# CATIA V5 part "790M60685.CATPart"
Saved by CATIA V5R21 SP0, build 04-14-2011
Part number: 790M60685
Bounding box of the stored display mesh (mm): x -342.5 to 342.5, y 0 to 61, z -122.5 to 122.5
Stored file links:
  C:\Users\ALI OZGUN\Desktop\alhan\790M60685.CATPart
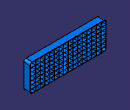
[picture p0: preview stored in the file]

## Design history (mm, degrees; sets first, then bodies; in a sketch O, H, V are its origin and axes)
Body1 (main body)
  Sketch1 on zx-plane, origin (0, 0, 0), H (-1, 0, 0), V (0, 0, 1)
    line L1 (342.5, 122.5) -> (342.5, -122.5)
    line L2 (342.5, -122.5) -> (-342.5, -122.5)
    line L3 (-342.5, -122.5) -> (-342.5, 122.5)
    line L4 (-342.5, 122.5) -> (342.5, 122.5)
    distance L4 L2 = 245
    distance L1 L3 = 685
    vertical: L1 V, L3 V
    horizontal: L2 H, L4 H
    equidistance: L1 L3 O, L2 L4 O
  Pad1: profile Sketch1, direction (0, 1, 0), length 60
  Fillet1: radius 20, on edge [face of Pad1 from Sketch1.L1 | face of Pad1 from Sketch1.L2]; edge [face of Pad1 from Sketch1.L2 | face of Pad1 from Sketch1.L3]; edge [face of Pad1 from Sketch1.L3 | face of Pad1 from Sketch1.L4]; edge [face of Pad1 from Sketch1.L4 | face of Pad1 from Sketch1.L1]
  Shell1: ExtOffset 0, Face (start face of Pad1; end face of Pad1), IntOffset 5
  Fillet2: radius 1, on edge [start face of Pad1 | face of Shell1]; edge [end face of Pad1 | face of Shell1]
  Fillet3: radius 2, on edge [start face of Pad1 | face of Pad1 from Sketch1.L1]; edge [end face of Pad1 | face of Fillet1]
  Sketch2 on start face of Pad1, origin (0, 0, 0), H (1, 0, 0), V (0, 0, 1)
    line L1 (-294, 118.5) -> (-294, -118.5)
    line L2 (-338.5, 82.5) -> (338.5, 82.5)
    projected line E9 (-338.5, -102.5) -> (-338.5, 102.5) from edge [face of Fillet2 | start face of Pad1]
    projected line E10 (-338.5, -102.5) -> (-338.5, 102.5) from edge [face of Fillet2 | start face of Pad1]
    projected line E12 (322.5, -118.5) -> (-322.5, -118.5) from edge [face of Fillet2 | start face of Pad1]
    projected line E13 (322.5, -118.5) -> (-322.5, -118.5) from edge [face of Fillet2 | start face of Pad1]
    projected line E15 (338.5, 102.5) -> (338.5, -102.5) from edge [face of Fillet2 | start face of Pad1]
    projected line E16 (338.5, 102.5) -> (338.5, -102.5) from edge [face of Fillet2 | start face of Pad1]
    projected line E18 (-322.5, 118.5) -> (322.5, 118.5) from edge [face of Fillet2 | start face of Pad1]
    projected line E19 (-322.5, 118.5) -> (322.5, 118.5) from edge [face of Fillet2 | start face of Pad1]
    reference intersected line E21 (-337.5, 102.5) -> (-337.5, -102.5) from face of Shell1
    reference intersected line E22 (322.5, 117.5) -> (-322.5, 117.5) from face of Shell1
    point P33 (-294, 118.5)
    point P34 (-338.5, 82.5)
    point P35 (-294, -118.5)
    point P36 (338.5, 82.5)
    line L3 (-338.5, 49.5) -> (338.5, 49.5)
    line L4 (-338.5, 16.5) -> (338.5, 16.5)
    line L5 (-338.5, -16.5) -> (338.5, -16.5)
    line L6 (-338.5, -49.5) -> (338.5, -49.5)
    line L7 (-338.5, -82.5) -> (338.5, -82.5)
    reference intersected line E23 (-322.5, -117.5) -> (322.5, -117.5) from face of Shell1
    line L8 (-252, 118.5) -> (-252, -118.5)
    line L9 (-210, 118.5) -> (-210, -118.5)
    line L10 (-168, 118.5) -> (-168, -118.5)
    line L11 (-126, 118.5) -> (-126, -118.5)
    line L12 (-84, 118.5) -> (-84, -118.5)
    line L13 (-42, 118.5) -> (-42, -118.5)
    line L14 (0, 118.5) -> (0, -118.5)
    line L15 (42, 118.5) -> (42, -118.5)
    line L16 (84, 118.5) -> (84, -118.5)
    line L17 (126, 118.5) -> (126, -118.5)
    line L18 (168, 118.5) -> (168, -118.5)
    line L19 (210, 118.5) -> (210, -118.5)
    line L20 (252, 118.5) -> (252, -118.5)
    line L21 (294, 118.5) -> (294, -118.5)
    reference intersected line E24 (337.5, -102.5) -> (337.5, 102.5) from face of Shell1
    distance L1 E21 = 43.5
    distance L2 E22 = 35
    distance L3 L2 = 33
    distance L3 L4 = 33
    distance L4 L5 = 33
    distance L5 L6 = 33
    distance L7 E23 = 35
    distance L6 L7 = 33 (reference)
    distance L21 L20 = 42
    distance L19 L20 = 42
    distance L18 L19 = 42
    distance L17 L18 = 42
    distance L16 L17 = 42
    distance L15 L16 = 42
    distance L14 L15 = 42
    distance L13 L14 = 42
    distance L12 L13 = 42
    distance L11 L12 = 42
    distance L10 L11 = 42
    distance L9 L10 = 42
    distance L8 L9 = 42
    distance L1 L8 = 42
    distance L21 E24 = 43.5 (reference)
    vertical: L1 V
    horizontal: L2 H
    coincidence: P33 E18, P34 E9, P35 E12, P36 E15
  Pad2: profile Sketch2, direction (0, 1, 0), length 61, thin wall 3
  Sketch3 on face of Pad2, origin (-295.5, 0, 0), H (0, -1, 0), V (0, 0, 1)
    construction line L1 (-60, -82.6932) -> (-60, 122.3068)
    construction line L2 (-60, -77.7415) -> (-60, 127.2585)
    line L3 (-60, 84) -> (-60, 88)
    line L4 (-61, 88) -> (-61, 84)
    line L5 (-60, 91.6965) -> (-60, 95.6965)
    line L6 (-61, 95.6965) -> (-61, 91.6965)
    construction line L7 (0, 91.6965) -> (-61, 91.6965)
    line L8 (-60, 91.6965) -> (-61, 91.6965)
    construction line L9 (0, 95.6965) -> (-61, 95.6965)
    construction line L10 (-60.5438, 95.6965) -> (-61, 95.6965)
    line L11 (-60, 95.6965) -> (-61, 95.6965)
    line L12 (-60, 97.893) -> (-61, 97.893)
    construction line L13 (0, 97.893) -> (-61, 97.893)
    line L14 (-60, 101.893) -> (-61, 101.893)
    construction line L15 (-60.5438, 101.893) -> (-61, 101.893)
    construction line L16 (0, 101.893) -> (-61, 101.893)
    line L17 (-60, 97.893) -> (-60, 101.893)
    line L18 (-61, 101.893) -> (-61, 97.893)
    line L19 (-60, 104.0895) -> (-61, 104.0895)
    construction line L20 (0, 104.0895) -> (-61, 104.0895)
    line L21 (-60, 108.0895) -> (-61, 108.0895)
    construction line L22 (-60.5438, 108.0895) -> (-61, 108.0895)
    construction line L23 (0, 108.0895) -> (-61, 108.0895)
    line L24 (-60, 104.0895) -> (-60, 108.0895)
    line L25 (-61, 108.0895) -> (-61, 104.0895)
    line L26 (-60, 110.286) -> (-61, 110.286)
    construction line L27 (0, 110.286) -> (-61, 110.286)
    line L28 (-60, 114.286) -> (-61, 114.286)
    construction line L29 (-60.5438, 114.286) -> (-61, 114.286)
    construction line L30 (0, 114.286) -> (-61, 114.286)
    line L31 (-60, 110.286) -> (-60, 114.286)
    line L32 (-61, 114.286) -> (-61, 110.286)
    line L33 (-60, 116.4825) -> (-61, 116.4825)
    construction line L34 (0, 116.4825) -> (-61, 116.4825)
    line L35 (-60, 120.4825) -> (-61, 120.4825)
    construction line L36 (-60.5438, 120.4825) -> (-61, 120.4825)
    construction line L37 (0, 120.4825) -> (-61, 120.4825)
    line L38 (-60, 116.4825) -> (-60, 120.4825)
    line L39 (-61, 120.4825) -> (-61, 116.4825)
    construction line L40 (0, 84) -> (-61, 84)
    line L41 (-60, 84) -> (-61, 84)
    construction line L42 (0, 88) -> (-61, 88)
    construction line L43 (-60.5438, 88) -> (-61, 88)
    line L44 (-60, 88) -> (-61, 88)
  Pocket1: profile Sketch3, direction (1, 0, 0), length 914
  Mirror1: of Pocket1, Sketch3, about xy-plane
  Sketch4 on face of Pad2, origin (-295.5, 0, 0), H (0, -1, 0), V (0, 0, 1)
    projected line E1 (-61, 81) -> (-61, 51) from edge [end face of Pad2 | face of Pad2]
    projected line E2 (-61, 55) -> (-61, 51) from edge [end face of Pad2 | face of Pad2]
    projected line E3 (0, 51) -> (-61, 51) from edge [face of Pad2 | face of Pad2]
    projected line E4 (-60, 51) -> (-61, 51) from edge [face of Pad2 | face of Pad2]
    offset line E5 (-60, 81) -> (-60, 51) from edge [end face of Pad2 | face of Pad2]
    offset line E6 (-60, 55) -> (-60, 51) from edge [end face of Pad2 | face of Pad2]
    offset line E7 (0, 55) -> (-61, 55) from edge [face of Pad2 | face of Pad2]
    offset line E8 (-60, 55) -> (-61, 55) from edge [face of Pad2 | face of Pad2]
    construction line L1 (0, 82.4462) -> (-61, 82.4462)
    construction line L2 (0, 78.5) -> (-61, 78.5)
    construction line L3 (-60.9437, 87.5779) -> (-61, 56.2)
    line L4 (-61, 60.2) -> (-61, 56.2)
    construction line L5 (0.0563, 57.5779) -> (-61, 56.2)
    line L6 (-60, 56.2) -> (-61, 56.2)
    construction line L7 (-59.9437, 87.5779) -> (-60, 56.2)
    line L8 (-60, 60.2) -> (-60, 56.2)
    construction line L9 (0.0563, 61.5779) -> (-61, 60.2)
    line L10 (-60, 60.2) -> (-61, 60.2)
    line L11 (-61, 65.4) -> (-61, 61.4)
    construction line L12 (-61, 91.4) -> (-61, 61.4)
    line L13 (-60, 61.4) -> (-61, 61.4)
    construction line L14 (0, 61.4) -> (-61, 61.4)
    line L15 (-60, 65.4) -> (-60, 61.4)
    construction line L16 (-60, 91.4) -> (-60, 61.4)
    line L17 (-60, 65.4) -> (-61, 65.4)
    construction line L18 (0, 65.4) -> (-61, 65.4)
    point P40 (-60, 66.6)
    line L19 (-61, 70.6) -> (-61, 66.6)
    construction line L20 (-61, 96.6) -> (-61, 66.6)
    line L21 (-60, 66.6) -> (-61, 66.6)
    construction line L22 (0, 66.6) -> (-61, 66.6)
    line L23 (-60, 70.6) -> (-60, 66.6)
    construction line L24 (-60, 96.6) -> (-60, 66.6)
    line L25 (-60, 70.6) -> (-61, 70.6)
    construction line L26 (0, 70.6) -> (-61, 70.6)
    line L27 (-61, 75.8) -> (-61, 71.8)
    construction line L28 (-60.9961, 102.287) -> (-61, 71.8)
    line L29 (-60, 71.8) -> (-61, 71.8)
    construction line L30 (0.0039, 72.287) -> (-61, 71.8)
    line L31 (-60, 75.8) -> (-60, 71.8)
    construction line L32 (-59.9961, 102.287) -> (-60, 71.8)
    line L33 (-60, 75.8) -> (-61, 75.8)
    construction line L34 (0.0039, 76.287) -> (-61, 75.8)
    line L35 (-61, 81) -> (-61, 77)
    construction line L36 (-61, 107) -> (-61, 77)
    line L37 (-60, 77) -> (-61, 77)
    construction line L38 (0, 77) -> (-61, 77)
    line L39 (-60, 81) -> (-60, 77)
    construction line L40 (-60, 108.3289) -> (-60, 78.3289)
    line L41 (-60, 81) -> (-61, 81)
    construction line L42 (0, 82.3289) -> (-61, 82.3289)
    distance L6 E7 = 1.2
    distance L13 L10 = 1.2
    distance P40 L17 = 1.2
    distance L29 L25 = 1.2
    coincidence: L8 E5, L15 L8, L23 L15, L31 L23
  Pocket2: profile Sketch4, direction (1, 0, 0), length 914
  RectPattern1: of Pocket2, direction 1 instances 5, spacing 33, along edge [end face of Pad2 | face of Pad2]
  Sketch5 on face of Pocket1, origin (0, 0, 84), H (1, 0, 0), V (0, 1, 0)
    projected line E1 (-338.5, 61) -> (338.5, 61) from edge [face of Pocket1 | end face of Pad2]
    projected line E2 (-292.5, 61) -> (-287.5, 61) from edge [face of Pocket1 | end face of Pad2]
    projected line E3 (-292.5, 0) -> (-292.5, 60) from edge [face of Pocket1 | face of Pad2]
    projected line E4 (-292.5, 60) -> (-292.5, 61) from edge [face of Pocket1 | face of Pad2]
    offset line E5 (-338.5, 60) -> (338.5, 60) from edge [face of Pocket1 | end face of Pad2]
    offset line E6 (-292.5, 60) -> (-287.5, 60) from edge [face of Pocket1 | end face of Pad2]
    offset line E7 (-287.5, 0) -> (-287.5, 60) from edge [face of Pocket1 | face of Pad2]
    offset line E8 (-287.5, 60) -> (-287.5, 61) from edge [face of Pocket1 | face of Pad2]
    construction line L1 (-273.9262, 0) -> (-273.9262, 60)
    line L2 (-273.9262, 60) -> (-273.9262, 61)
    construction line L3 (-321.4262, 61) -> (355.5738, 61)
    line L4 (-273.9262, 61) -> (-268.9262, 61)
    construction line L5 (-268.9262, 0) -> (-268.9262, 60)
    line L6 (-268.9262, 60) -> (-268.9262, 61)
    construction line L7 (-321.4262, 60) -> (355.5738, 60)
    line L8 (-273.9262, 60) -> (-268.9262, 60)
    line L9 (-258.5, 60) -> (-258.5, 61)
    construction line L10 (-256.8524, 0) -> (-256.8524, 60)
    line L11 (-258.5, 61) -> (-253.5, 61)
    construction line L12 (-304.3524, 61) -> (372.6476, 61)
    line L13 (-253.5, 60) -> (-253.5, 61)
    construction line L14 (-251.8524, 0) -> (-251.8524, 60)
    line L15 (-258.5, 60) -> (-253.5, 60)
    construction line L16 (-304.3524, 60) -> (372.6476, 60)
    reference intersected line E9 (-253.5, 0) -> (-253.5, 61) from face of Pad2
    coincidence: L13 E9
  Pocket3: profile Sketch5, direction (0, 0, -1), length 914
  RectPattern2: of Pocket3, direction 1 instances 14, spacing 42, along edge [face of Pocket1 | end face of Pad2]
  Sketch6 on face of Pocket1, origin (0, 0, 84), H (1, 0, 0), V (0, 1, 0)
    projected line E1 (292.5, 61) -> (338.5, 61) from edge [face of Pocket1 | end face of Pad2]
    projected line E2 (295.5, 61) -> (300.5, 61) from edge [face of Pocket1 | end face of Pad2]
    projected line E3 (295.5, 0) -> (295.5, 60) from edge [face of Pocket1 | face of Pad2]
    projected line E4 (295.5, 60) -> (295.5, 61) from edge [face of Pocket1 | face of Pad2]
    offset line E5 (300.5, 0) -> (300.5, 60) from edge [face of Pocket1 | face of Pad2]
    offset line E6 (300.5, 60) -> (300.5, 61) from edge [face of Pocket1 | face of Pad2]
    offset line E7 (292.5, 60) -> (338.5, 60) from edge [face of Pocket1 | end face of Pad2]
    offset line E8 (295.5, 60) -> (300.5, 60) from edge [face of Pocket1 | end face of Pad2]
    construction line L1 (315.256, 0) -> (315.256, 60)
    line L2 (315.256, 60) -> (315.256, 61)
    construction line L3 (312.256, 61) -> (356.756, 61)
    line L4 (315.256, 61) -> (320.256, 61)
    construction line L5 (312.256, 60) -> (356.756, 60)
    line L6 (315.256, 60) -> (320.256, 60)
    construction line L7 (320.256, 0) -> (320.256, 60)
    line L8 (320.256, 60) -> (320.256, 61)
    line L9 (333.5119, 60) -> (333.5119, 61)
    construction line L10 (333.5119, 0) -> (333.5119, 60)
    line L11 (333.5119, 61) -> (338.5119, 61)
    construction line L12 (330.5119, 61) -> (375.0119, 61)
    line L13 (333.5119, 60) -> (338.5119, 60)
    construction line L14 (330.5119, 60) -> (375.0119, 60)
    line L15 (338.5119, 60) -> (338.5119, 61)
    construction line L16 (338.5119, 0) -> (338.5119, 60)
  Pocket4: profile Sketch6, direction (0, 0, -1), length 914
  RectPattern3: of Pocket4, direction 1 instances 2, spacing 634, along edge [face of Pocket1 | end face of Pad2] reversed
  Sketch7 on face of Pad2, origin (0, 0, 0), H (1, 0, 0), V (0, 0, 1)
    circle A1 centre (-321.5, -102.5) radius 10
    circle A2 centre (-321.5, -102.5) radius 8
    reference projected line E1 (322.5, -122.5) -> (-322.5, -122.5) from edge [face of Fillet3 | face of Pad1 from Sketch1.L2]
    reference projected line E2 (-342.5, -102.5) -> (-342.5, 102.5) from edge [face of Fillet3 | face of Pad1 from Sketch1.L1]
    circle A3 centre (-321.5, 102.5) radius 10
    circle A4 centre (-321.5, 102.5) radius 8
    circle A5 centre (321.5, -102.5) radius 10
    circle A6 centre (321.5, -102.5) radius 8
    circle A7 centre (321.5, 102.5) radius 10
    circle A8 centre (321.5, 102.5) radius 8
    radius A2 = 8
    radius A1 = 10
    distance A2 E1 = 12
    distance A2 E2 = 13
    symmetry: A1 A3 H, A2 A4 H, A1 A5 V, A2 A6 V, A3 A7 V, A4 A8 V
  Pad3: profile Sketch7, direction (0, 1, 0), length 40, opposite side length -1
  Sketch8 on end face of Pad3, origin (0, 40, 0), H (-1, 0, 0), V (0, 0, 1)
    reference projected circle E1 centre (321.5, 102.5) radius 8 from edge [face of Pad3 from Sketch7.A4 | end face of Pad3]
    line L1 (329.4987, 102.6424) -> (339.7094, 102.6424)
    point P1 (329.4987, 102.6424)
    point P2 (339.7094, 102.6424)
    line L2 (321.6707, 110.4982) -> (321.6707, 119.3862)
    point P3 (321.6707, 110.4982)
    point P4 (321.6707, 119.3862)
    line L3 (313.5013, 102.6424) -> (294.1505, 102.6424)
    point P5 (313.5013, 102.6424)
    point P6 (294.1505, 102.6424)
    line L4 (321.6707, 94.5018) -> (321.6707, 82.7352)
    point P7 (321.6707, 94.5018)
    point P8 (321.6707, 82.7352)
    point P9 (329.4987, -102.6424)
    point P10 (339.7094, -102.6424)
    point P11 (321.6707, -110.4982)
    point P12 (321.6707, -119.3862)
    point P13 (313.5013, -102.6424)
    point P14 (294.1505, -102.6424)
    point P15 (321.6707, -94.5018)
    point P16 (321.6707, -82.7352)
    line L5 (329.4987, -102.6424) -> (339.7094, -102.6424)
    line L6 (321.6707, -110.4982) -> (321.6707, -119.3862)
    line L7 (313.5013, -102.6424) -> (294.1505, -102.6424)
    line L8 (321.6707, -94.5018) -> (321.6707, -82.7352)
    construction circle A1 centre (321.5, -102.5) radius 8
    point P17 (-329.4987, 102.6424)
    point P18 (-339.7094, 102.6424)
    point P19 (-321.6707, 110.4982)
    point P20 (-321.6707, 119.3862)
    point P21 (-313.5013, 102.6424)
    point P22 (-294.1505, 102.6424)
    point P23 (-321.6707, 94.5018)
    point P24 (-321.6707, 82.7352)
    point P25 (-329.4987, -102.6424)
    point P26 (-339.7094, -102.6424)
    point P27 (-321.6707, -110.4982)
    point P28 (-321.6707, -119.3862)
    point P29 (-313.5013, -102.6424)
    point P30 (-294.1505, -102.6424)
    point P31 (-321.6707, -94.5018)
    point P32 (-321.6707, -82.7352)
    construction circle A2 centre (-321.5, -102.5) radius 8
    line L9 (-329.4987, 102.6424) -> (-339.7094, 102.6424)
    line L10 (-321.6707, 110.4982) -> (-321.6707, 119.3862)
    line L11 (-313.5013, 102.6424) -> (-294.1505, 102.6424)
    line L12 (-321.6707, 94.5018) -> (-321.6707, 82.7352)
    line L13 (-329.4987, -102.6424) -> (-339.7094, -102.6424)
    line L14 (-321.6707, -110.4982) -> (-321.6707, -119.3862)
    line L15 (-313.5013, -102.6424) -> (-294.1505, -102.6424)
    line L16 (-321.6707, -94.5018) -> (-321.6707, -82.7352)
    construction circle A3 centre (-321.5, 102.5) radius 8
    coincidence: P1 E1, P3 E1, P5 L1, P5 E1, P7 L2, P7 E1
    horizontal: L1 H, L3 H
    vertical: L2 V, L4 V
    symmetry: P1 P9 H, P2 P10 H, P3 P11 H, P4 P12 H, P5 P13 H, P6 P14 H, P7 P15 H, P8 P16 H, E1 A1 H, L1 L5 H, L2 L6 H, L3 L7 H, L4 L8 H, E1 A3 V, P1 P17 V, P2 P18 V, P3 P19 V, P4 P20 V, P5 P21 V, P6 P22 V, P7 P23 V, P8 P24 V, P9 P25 V, P10 P26 V, P11 P27 V, P12 P28 V, P13 P29 V, P14 P30 V, P15 P31 V, P16 P32 V, A1 A2 V, L1 L9 V, L2 L10 V, L3 L11 V, L4 L12 V, L5 L13 V, L6 L14 V, L7 L15 V, L8 L16 V
  Pad4: profile Sketch8, direction (0, -1, 0), length 39, thin wall 3
  Sketch9 on face of Pad4, origin (0, 1, 0), H (1, 0, 0), V (0, 0, 1)
    circle A1 centre (-321.5, -102.5) radius 12.5
    point P1 (-321.5, -102.5)
    reference projected arc E1 centre (-321.5, -102.5) radius 8 from (-329.4987, -102.6424) to (-321.6707, -110.4982) ccw from edge [face of Pad4 | face of Pad3 from Sketch7.A2]
    circle A2 centre (-321.5, -102.5) radius 8
    reference projected arc E5 centre (-321.5, -102.5) radius 8 from (-329.4987, -102.6424) to (-321.6707, -110.4982) ccw from edge [face of Pad4 | face of Pad3 from Sketch7.A2]
    circle A3 centre (-321.5, 102.5) radius 12.5
    circle A4 centre (-321.5, 102.5) radius 8
    circle A5 centre (321.5, -102.5) radius 12.5
    circle A6 centre (321.5, -102.5) radius 8
    circle A7 centre (321.5, 102.5) radius 12.5
    circle A8 centre (321.5, 102.5) radius 8
    radius A1 = 12.5
    concentricity: P1 E1
    tangency: A2 E5
    symmetry: A1 A3 H, A2 A4 H, A1 A5 V, A2 A6 V, A3 A7 V, A4 A8 V
  Pad5: profile Sketch9, direction (0, 1, 0), length 15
